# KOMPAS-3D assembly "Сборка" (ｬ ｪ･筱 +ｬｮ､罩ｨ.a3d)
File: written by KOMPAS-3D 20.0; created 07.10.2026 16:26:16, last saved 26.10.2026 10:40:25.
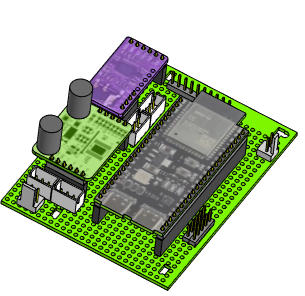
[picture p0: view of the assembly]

Document properties: Полное имя файла: D:\RicWork\Project-EPS32\box_compas\сборки компонентов\макетка+модули.a3d

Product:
- Part/product: Сборка
    Масса: 0.132529
  - Component [assembly]: Сборка  | Масса: 0.0386432; source file: ..\esp32\esp32-s3-n16r8_asm+.a3d
  - Component [detail]: Деталь  | Масса: 0.00147109; source file: ..\разъемы\WF-3 (DS1070-3 M).m3d
  - Component [detail]: Деталь  | qty 4  | Масса: 0.00117184; source file: ..\разъемы\B3B-XH-A.m3d
  - Component [assembly]: Сборка  | Масса: 0.0106182; source file: ..\цап ацп\pcm5102A_asm+.a3d
  - Component [detail]: Деталь  | qty 2  | Масса: 0.000651758; source file: ..\разъемы\pls_5.m3d
  - Component [detail]: Деталь  | Масса: 0.0509676; source file: ..\макетки\Макетная плата_01.m3d
  - Component [assembly]: Сборка  | Масса: 0.0226054; source file: ..\усилитель\HT8698_asm+.a3d
  - Component [detail]: Деталь  | Масса: 0.000929543; source file: ..\разъемы\WF-2 (DS1070-2 M).m3d
  - Component [detail]: Деталь  | Масса: 0.00130352; source file: ..\разъемы\pls_10.m3d

Referenced files in D:\RicWork\Project-EPS32\box_compas\макетки\: Макетная плата_01.m3d
Referenced files in D:\RicWork\Project-EPS32\box_compas\разъемы\: pls_5.m3d, B3B-XH-A.m3d, WF-3 (DS1070-3 M).m3d, WF-2 (DS1070-2 M).m3d, pls_10.m3d
Referenced files in D:\RicWork\Project-EPS32\box_compas\усилитель\: HT8698_asm+.a3d
Referenced files in D:\RicWork\Project-EPS32\box_compas\цап ацп\: pcm5102A_asm+.a3d
Referenced files in D:\RicWork\Project-EPS32\box_compas\esp32\: esp32-s3-n16r8_asm+.a3d
Referenced files in D:\myProjects\Progect_esp32\box_compas\разъемы\: B3B-XH-A.m3d, WF-3 (DS1070-3 M).m3d
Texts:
  Деталь (1)
  Деталь (2)
  Деталь (3)
  Деталь (4)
